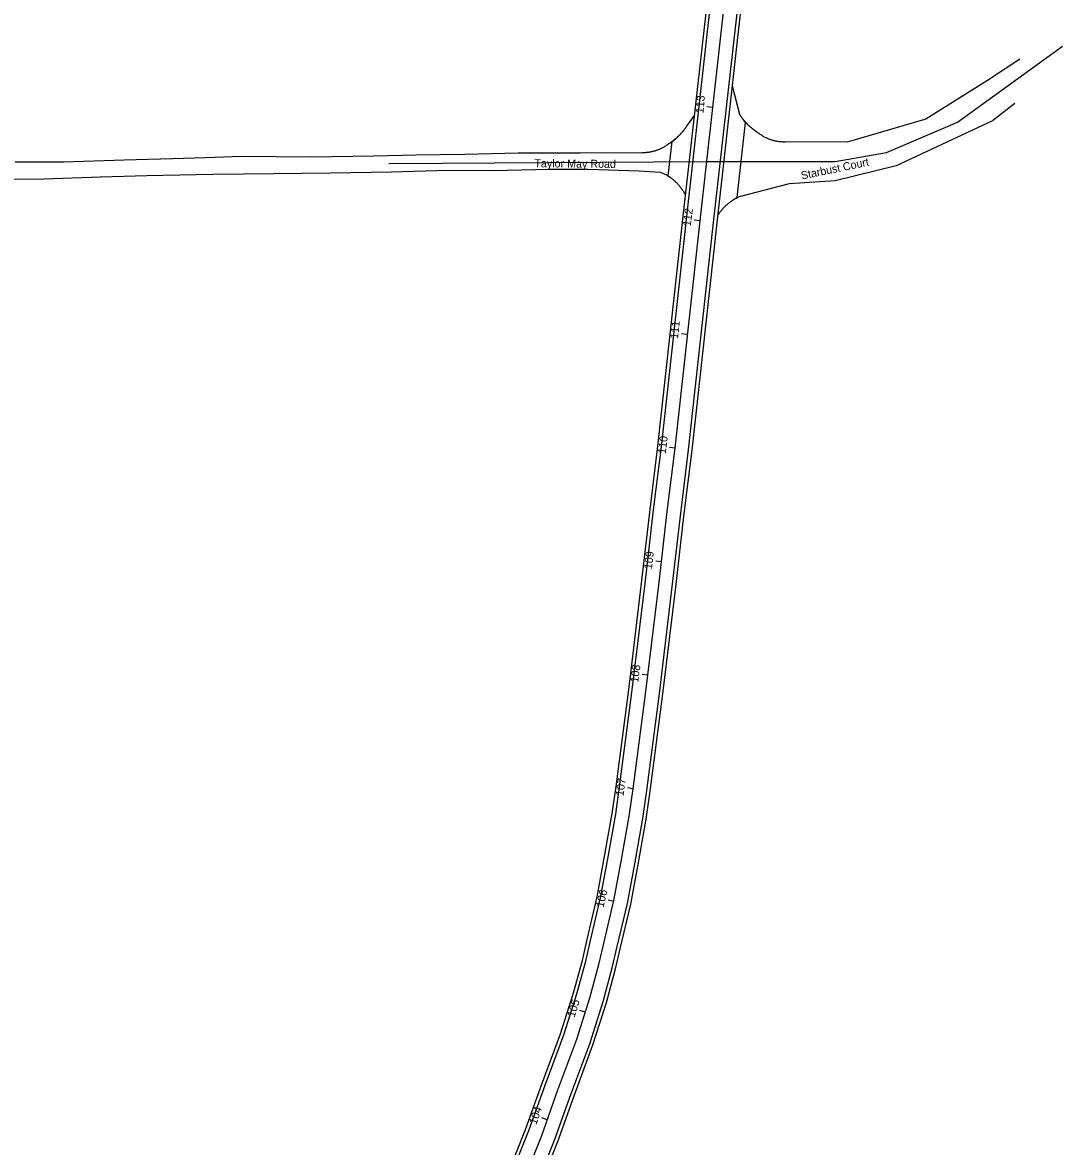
# Model space of a CAD drawing. Extents: x 2318076 to 2324211, y 613525 to 629939.
# Drawn here: x 2319710 to 2320620, y 624977 to 625960 of the extents above; entities that cross this region are included whole.
import ezdxf

# ---------------------------------------------------------------- set-up
doc = ezdxf.new("R2010")
doc.units = 0
for name, color, linetype in [('GE_P_CL_50', 7, 'Continuous'), ('GE_X_CL_50', 7, 'Continuous'), ('PV_P_EOP', 7, 'Continuous'), ('PV_P_Shoulder', 7, 'Continuous'), ('RS_Raster1', 7, 'Continuous')]:
    doc.layers.add(name, color=color, linetype=linetype)

msp = doc.modelspace()

# ---------------------------------------------------------------- linework, layer by layer
at = {"layer": 'GE_P_CL_50'}
for p, q in [((2320313.51, 625885.5), (2320308.52, 625885.92)), ((2320302.51, 625786.14), (2320297.55, 625786.8)), ((2320291.21, 625686.79), (2320286.24, 625687.31)), ((2320280.66, 625587.35), (2320275.69, 625587.96)), ((2320268.76, 625488.06), (2320263.79, 625488.64)), ((2320256.86, 625388.77), (2320251.9, 625389.39)), ((2320244.08, 625289.6), (2320239.13, 625290.3)), ((2320227.1, 625191.06), (2320222.24, 625192.22)), ((2320202.23, 625094.25), (2320197.46, 625095.76)), ((2320168.9, 624999.98), (2320164.19, 625001.66))]:
    msp.add_line(p, q, dxfattribs=at)
msp.add_lwpolyline([(2320140.16, 624926.58), (2320164.06, 624986.38), (2320178.23, 625026.18), (2320194.66, 625070.42), (2320206.22, 625106.83), (2320214.16, 625135.77), (2320218.35, 625154.25), (2320227.28, 625191.8), (2320233.59, 625226.06), (2320240.64, 625265.45), (2320244.08, 625289.6), (2320254.79, 625372.16), (2320256.86, 625388.77), (2320266.38, 625467.61), (2320273.88, 625532.13), (2320280.66, 625587.35), (2320302.51, 625786.14), (2320324.84, 625984.85)], dxfattribs=at)
at = {"layer": 'GE_X_CL_50'}
msp.add_line((2320030.25, 625836.28), (2320308.36, 625838.18), dxfattribs=at)
msp.add_lwpolyline([(2320308.36, 625838.18), (2320420.71, 625838.18), (2320465.73, 625845.99), (2320527.77, 625872.59), (2320619.58, 625938.92)], dxfattribs=at)
at = {"layer": 'PV_P_EOP'}
for p, q in [((2320337.34, 625879.18), (2320330.86, 625904.07)), ((2320291.58, 625870.03), (2320297.78, 625878.38))]:
    msp.add_line(p, q, dxfattribs=at)
for points in [[(2320129, 624931), (2320152.83, 624990.62), (2320166.95, 625030.28), (2320183.31, 625074.33), (2320194.71, 625110.23), (2320202.52, 625138.69), (2320206.66, 625156.96), (2320215.53, 625194.28), (2320221.78, 625228.2), (2320228.79, 625267.35), (2320232.19, 625291.22), (2320242.89, 625373.68), (2320244.95, 625390.24), (2320254.46, 625469.02), (2320261.96, 625533.55), (2320268.74, 625588.74), (2320290.58, 625787.47), (2320312.9, 625986.1)], [(2320151.32, 624922.16), (2320175.29, 624982.14), (2320189.51, 625022.08), (2320206.01, 625066.51), (2320217.73, 625103.43), (2320225.8, 625132.85), (2320230.04, 625151.54), (2320239.03, 625189.32), (2320245.4, 625223.92), (2320252.49, 625263.55), (2320255.97, 625287.98), (2320266.69, 625370.64), (2320268.77, 625387.31), (2320278.3, 625466.2), (2320285.8, 625530.71), (2320292.57, 625585.97), (2320314.44, 625784.81), (2320336.77, 625983.61)], [(2320342.39, 625872.41), (2320340.78, 625874.39), (2320340.66, 625874.53), (2320340.54, 625874.68), (2320340.43, 625874.82), (2320340.32, 625874.97), (2320340.2, 625875.11), (2320340.09, 625875.26), (2320339.98, 625875.4), (2320339.86, 625875.55), (2320339.75, 625875.7), (2320339.64, 625875.84), (2320339.53, 625875.99), (2320339.42, 625876.14), (2320339.31, 625876.29), (2320339.2, 625876.44), (2320339.1, 625876.59), (2320338.99, 625876.74), (2320338.88, 625876.89), (2320338.77, 625877.04), (2320338.67, 625877.19), (2320338.56, 625877.34), (2320338.46, 625877.49), (2320338.35, 625877.64), (2320338.25, 625877.79), (2320338.14, 625877.95), (2320338.04, 625878.1), (2320337.94, 625878.25), (2320337.84, 625878.41), (2320337.74, 625878.56), (2320337.63, 625878.71), (2320337.53, 625878.87), (2320337.43, 625879.02), (2320337.34, 625879.18)], [(2320278.11, 625855.59), (2320281.04, 625858.03), (2320281.18, 625858.15), (2320281.32, 625858.27), (2320281.46, 625858.39), (2320281.6, 625858.51), (2320281.74, 625858.63), (2320281.88, 625858.75), (2320282.02, 625858.87), (2320282.16, 625858.99), (2320282.3, 625859.11), (2320282.43, 625859.24), (2320282.57, 625859.36), (2320282.71, 625859.48), (2320282.84, 625859.61), (2320282.98, 625859.73), (2320283.11, 625859.86), (2320283.25, 625859.98), (2320283.38, 625860.11), (2320283.52, 625860.24), (2320283.65, 625860.36), (2320283.78, 625860.49), (2320283.92, 625860.62), (2320284.05, 625860.75), (2320284.18, 625860.88), (2320284.31, 625861.01), (2320284.44, 625861.14), (2320284.57, 625861.27), (2320284.7, 625861.4), (2320284.83, 625861.53), (2320284.96, 625861.66), (2320285.09, 625861.79), (2320285.22, 625861.92), (2320285.34, 625862.06), (2320285.47, 625862.19), (2320285.6, 625862.33), (2320285.72, 625862.46), (2320285.85, 625862.6), (2320285.97, 625862.73), (2320286.1, 625862.87), (2320286.22, 625863), (2320286.35, 625863.14), (2320286.47, 625863.28), (2320286.59, 625863.41), (2320286.71, 625863.55), (2320286.84, 625863.69), (2320286.96, 625863.83), (2320287.08, 625863.97), (2320287.2, 625864.11), (2320287.32, 625864.25), (2320287.44, 625864.39), (2320287.55, 625864.53), (2320287.67, 625864.67), (2320287.79, 625864.81), (2320287.91, 625864.96), (2320288.02, 625865.1), (2320288.14, 625865.24), (2320288.26, 625865.39), (2320288.37, 625865.53), (2320288.49, 625865.67), (2320288.6, 625865.82), (2320288.71, 625865.96), (2320288.83, 625866.11), (2320288.94, 625866.26), (2320289.05, 625866.4), (2320289.16, 625866.55), (2320289.27, 625866.7), (2320289.38, 625866.84), (2320289.49, 625866.99), (2320289.6, 625867.14), (2320289.71, 625867.29), (2320289.82, 625867.44), (2320289.93, 625867.59), (2320290.04, 625867.74), (2320290.14, 625867.89), (2320290.25, 625868.04), (2320290.35, 625868.19), (2320290.46, 625868.34), (2320290.56, 625868.49), (2320290.67, 625868.64), (2320290.77, 625868.8), (2320290.87, 625868.95), (2320290.98, 625869.1), (2320291.08, 625869.26), (2320291.18, 625869.41), (2320291.28, 625869.56), (2320291.38, 625869.72), (2320291.48, 625869.87), (2320291.58, 625870.03)], [(2320334.98, 625806.54), (2320342.39, 625872.41)], [(2320274.73, 625825.51), (2320278.11, 625855.59)], [(2320274.73, 625825.51), (2320276.76, 625824.08), (2320277.34, 625823.65), (2320277.92, 625823.21), (2320278.49, 625822.77), (2320279.05, 625822.31), (2320279.61, 625821.84), (2320280.15, 625821.37), (2320280.69, 625820.88), (2320281.22, 625820.39), (2320281.74, 625819.89), (2320282.25, 625819.37), (2320282.75, 625818.85), (2320283.24, 625818.32), (2320283.73, 625817.79), (2320284.2, 625817.24), (2320284.67, 625816.69), (2320285.12, 625816.12), (2320285.57, 625815.56), (2320286.01, 625814.98), (2320286.43, 625814.39), (2320286.85, 625813.8), (2320287.25, 625813.2), (2320287.65, 625812.6), (2320288.03, 625811.99), (2320289.96, 625808.8)], [(2320334.98, 625806.54), (2320331.51, 625804.43), (2320330.89, 625804.04), (2320330.29, 625803.64), (2320329.69, 625803.24), (2320329.1, 625802.82), (2320328.51, 625802.39), (2320327.94, 625801.95), (2320327.37, 625801.51), (2320326.81, 625801.05), (2320326.25, 625800.58), (2320325.71, 625800.11), (2320325.17, 625799.62), (2320324.64, 625799.13), (2320324.12, 625798.63), (2320323.61, 625798.11), (2320323.11, 625797.59), (2320322.62, 625797.06), (2320322.13, 625796.53), (2320321.66, 625795.98), (2320321.19, 625795.43), (2320320.74, 625794.86), (2320320.29, 625794.3), (2320319.85, 625793.72), (2320319.43, 625793.13), (2320319.01, 625792.54), (2320318.61, 625791.94), (2320318.21, 625791.34), (2320318.18, 625791.3)]]:
    msp.add_lwpolyline(points, dxfattribs=at)
at = {"layer": 'PV_P_Shoulder'}
for points in [[(2320126.21, 624932.11), (2320150.02, 624991.68), (2320164.13, 625031.31), (2320180.47, 625075.3), (2320191.83, 625111.09), (2320199.61, 625139.41), (2320203.74, 625157.64), (2320212.6, 625194.9), (2320218.83, 625228.74), (2320225.83, 625267.83), (2320229.21, 625291.62), (2320239.91, 625374.05), (2320241.97, 625390.6), (2320251.48, 625469.37), (2320258.99, 625533.91), (2320265.76, 625589.09), (2320287.6, 625787.8), (2320309.92, 625986.41)], [(2320154.11, 624921.05), (2320178.1, 624981.08), (2320192.33, 625021.05), (2320208.85, 625065.54), (2320220.61, 625102.57), (2320228.71, 625132.13), (2320232.96, 625150.86), (2320241.96, 625188.7), (2320248.35, 625223.38), (2320255.45, 625263.07), (2320258.94, 625287.58), (2320269.67, 625370.27), (2320271.75, 625386.95), (2320281.28, 625465.85), (2320288.77, 625530.35), (2320295.55, 625585.62), (2320317.42, 625784.48), (2320339.76, 625983.3)]]:
    msp.add_lwpolyline(points, dxfattribs=at)
at = {"layer": 'RS_Raster1'}
for p, q in [((2320337.34, 625879.18), (2320330.86, 625904.07)), ((2320291.58, 625870.03), (2320295.4, 625875.18))]:
    msp.add_line(p, q, dxfattribs=at)
for points in [[(2320582.17, 625927.61), (2320553.95, 625908.96), (2320499.97, 625875.32), (2320431.25, 625854.95), (2320377.43, 625855.23)], [(2320577.81, 625888.97), (2320558.36, 625873.67), (2320474.08, 625834.52), (2320420.65, 625821.28), (2320380.43, 625818.53), (2320337.96, 625807.69)], [(2320353.7, 625862.97), (2320353.54, 625863.07), (2320353.38, 625863.16), (2320353.23, 625863.26), (2320353.07, 625863.36), (2320352.92, 625863.46), (2320352.76, 625863.56), (2320352.61, 625863.66), (2320352.46, 625863.77), (2320352.3, 625863.87), (2320352.15, 625863.97), (2320352, 625864.07), (2320351.84, 625864.18), (2320351.69, 625864.28), (2320351.54, 625864.39), (2320351.39, 625864.49), (2320351.24, 625864.6), (2320351.09, 625864.7), (2320350.94, 625864.81), (2320350.79, 625864.92), (2320350.64, 625865.03), (2320350.49, 625865.14), (2320350.34, 625865.24), (2320350.19, 625865.35), (2320350.05, 625865.46), (2320349.9, 625865.57), (2320349.75, 625865.69), (2320349.6, 625865.8), (2320349.46, 625865.91), (2320349.31, 625866.02), (2320349.17, 625866.14), (2320349.02, 625866.25), (2320348.88, 625866.36), (2320348.73, 625866.48), (2320348.59, 625866.59), (2320348.45, 625866.71), (2320348.3, 625866.83), (2320348.16, 625866.94), (2320348.02, 625867.06), (2320347.88, 625867.18), (2320347.74, 625867.3), (2320347.59, 625867.42), (2320347.45, 625867.53), (2320347.31, 625867.65), (2320347.17, 625867.77), (2320347.04, 625867.9), (2320346.9, 625868.02), (2320346.76, 625868.14), (2320346.62, 625868.26), (2320346.48, 625868.38), (2320346.35, 625868.51), (2320346.21, 625868.63), (2320346.07, 625868.76), (2320345.94, 625868.88), (2320345.8, 625869.01), (2320345.67, 625869.13), (2320345.53, 625869.26), (2320345.4, 625869.38), (2320345.27, 625869.51), (2320345.13, 625869.64), (2320345, 625869.77), (2320344.87, 625869.9), (2320344.74, 625870.02), (2320344.61, 625870.15), (2320344.47, 625870.28), (2320344.34, 625870.41), (2320344.21, 625870.55), (2320344.09, 625870.68), (2320343.96, 625870.81), (2320343.83, 625870.94), (2320343.7, 625871.07), (2320343.57, 625871.21), (2320343.45, 625871.34), (2320343.32, 625871.47), (2320343.19, 625871.61), (2320343.07, 625871.74), (2320342.94, 625871.88), (2320342.82, 625872.02), (2320342.69, 625872.15), (2320342.57, 625872.29), (2320342.45, 625872.43), (2320342.32, 625872.56), (2320342.2, 625872.7), (2320342.08, 625872.84), (2320341.96, 625872.98), (2320341.84, 625873.12), (2320341.72, 625873.26), (2320341.6, 625873.4), (2320341.48, 625873.54), (2320341.36, 625873.68), (2320341.24, 625873.82), (2320341.13, 625873.96), (2320341.01, 625874.11), (2320340.89, 625874.25), (2320340.78, 625874.39), (2320340.66, 625874.53), (2320340.54, 625874.68), (2320340.43, 625874.82), (2320340.32, 625874.97), (2320340.2, 625875.11), (2320340.09, 625875.26), (2320339.98, 625875.4), (2320339.86, 625875.55), (2320339.75, 625875.7), (2320339.64, 625875.84), (2320339.53, 625875.99), (2320339.42, 625876.14), (2320339.31, 625876.29), (2320339.2, 625876.44), (2320339.1, 625876.59), (2320338.99, 625876.74), (2320338.88, 625876.89), (2320338.77, 625877.04), (2320338.67, 625877.19), (2320338.56, 625877.34), (2320338.46, 625877.49), (2320338.35, 625877.64), (2320338.25, 625877.79), (2320338.14, 625877.95), (2320338.04, 625878.1), (2320337.94, 625878.25), (2320337.84, 625878.41), (2320337.74, 625878.56), (2320337.63, 625878.71), (2320337.53, 625878.87), (2320337.43, 625879.02), (2320337.34, 625879.18)], [(2320275.22, 625853.82), (2320275.38, 625853.92), (2320275.53, 625854.02), (2320275.69, 625854.11), (2320275.84, 625854.21), (2320276, 625854.31), (2320276.15, 625854.41), (2320276.31, 625854.52), (2320276.46, 625854.62), (2320276.61, 625854.72), (2320276.77, 625854.82), (2320276.92, 625854.92), (2320277.07, 625855.03), (2320277.22, 625855.13), (2320277.38, 625855.24), (2320277.53, 625855.34), (2320277.68, 625855.45), (2320277.83, 625855.56), (2320277.98, 625855.66), (2320278.13, 625855.77), (2320278.28, 625855.88), (2320278.43, 625855.99), (2320278.57, 625856.1), (2320278.72, 625856.21), (2320278.87, 625856.32), (2320279.02, 625856.43), (2320279.16, 625856.54), (2320279.31, 625856.65), (2320279.46, 625856.76), (2320279.6, 625856.87), (2320279.75, 625856.99), (2320279.89, 625857.1), (2320280.04, 625857.22), (2320280.18, 625857.33), (2320280.33, 625857.45), (2320280.47, 625857.56), (2320280.61, 625857.68), (2320280.76, 625857.79), (2320280.9, 625857.91), (2320281.04, 625858.03), (2320281.18, 625858.15), (2320281.32, 625858.27), (2320281.46, 625858.39), (2320281.6, 625858.51), (2320281.74, 625858.63), (2320281.88, 625858.75), (2320282.02, 625858.87), (2320282.16, 625858.99), (2320282.3, 625859.11), (2320282.43, 625859.24), (2320282.57, 625859.36), (2320282.71, 625859.48), (2320282.84, 625859.61), (2320282.98, 625859.73), (2320283.11, 625859.86), (2320283.25, 625859.98), (2320283.38, 625860.11), (2320283.52, 625860.24), (2320283.65, 625860.36), (2320283.78, 625860.49), (2320283.92, 625860.62), (2320284.05, 625860.75), (2320284.18, 625860.88), (2320284.31, 625861.01), (2320284.44, 625861.14), (2320284.57, 625861.27), (2320284.7, 625861.4), (2320284.83, 625861.53), (2320284.96, 625861.66), (2320285.09, 625861.79), (2320285.22, 625861.92), (2320285.34, 625862.06), (2320285.47, 625862.19), (2320285.6, 625862.33), (2320285.72, 625862.46), (2320285.85, 625862.6), (2320285.97, 625862.73), (2320286.1, 625862.87), (2320286.22, 625863), (2320286.35, 625863.14), (2320286.47, 625863.28), (2320286.59, 625863.41), (2320286.71, 625863.55), (2320286.84, 625863.69), (2320286.96, 625863.83), (2320287.08, 625863.97), (2320287.2, 625864.11), (2320287.32, 625864.25), (2320287.44, 625864.39), (2320287.55, 625864.53), (2320287.67, 625864.67), (2320287.79, 625864.81), (2320287.91, 625864.96), (2320288.02, 625865.1), (2320288.14, 625865.24), (2320288.26, 625865.39), (2320288.37, 625865.53), (2320288.49, 625865.67), (2320288.6, 625865.82), (2320288.71, 625865.96), (2320288.83, 625866.11), (2320288.94, 625866.26), (2320289.05, 625866.4), (2320289.16, 625866.55), (2320289.27, 625866.7), (2320289.38, 625866.84), (2320289.49, 625866.99), (2320289.6, 625867.14), (2320289.71, 625867.29), (2320289.82, 625867.44), (2320289.93, 625867.59), (2320290.04, 625867.74), (2320290.14, 625867.89), (2320290.25, 625868.04), (2320290.35, 625868.19), (2320290.46, 625868.34), (2320290.56, 625868.49), (2320290.67, 625868.64), (2320290.77, 625868.8), (2320290.87, 625868.95), (2320290.98, 625869.1), (2320291.08, 625869.26), (2320291.18, 625869.41), (2320291.28, 625869.56), (2320291.38, 625869.72), (2320291.48, 625869.87), (2320291.58, 625870.03)], [(2320377.43, 625855.23), (2320376.81, 625855.21), (2320376.18, 625855.21), (2320375.56, 625855.21), (2320374.94, 625855.23), (2320374.32, 625855.25), (2320373.7, 625855.29), (2320373.08, 625855.33), (2320372.46, 625855.39), (2320371.85, 625855.46), (2320371.23, 625855.54), (2320370.61, 625855.63), (2320370, 625855.73), (2320369.39, 625855.84), (2320368.78, 625855.96), (2320368.17, 625856.09), (2320367.57, 625856.23), (2320366.97, 625856.38), (2320366.37, 625856.55), (2320365.77, 625856.72), (2320365.17, 625856.9), (2320364.58, 625857.09), (2320364, 625857.3), (2320363.41, 625857.51), (2320362.83, 625857.73), (2320362.26, 625857.96), (2320361.68, 625858.21), (2320361.11, 625858.46), (2320360.55, 625858.72), (2320359.99, 625858.99), (2320359.44, 625859.27), (2320358.89, 625859.56), (2320358.34, 625859.86), (2320357.8, 625860.17), (2320357.27, 625860.49), (2320356.74, 625860.82), (2320356.22, 625861.16), (2320355.7, 625861.5), (2320355.19, 625861.85), (2320354.69, 625862.22), (2320354.19, 625862.59), (2320353.7, 625862.97)], [(2320251.49, 625846.08), (2320252.11, 625846.06), (2320252.73, 625846.06), (2320253.35, 625846.06), (2320253.97, 625846.08), (2320254.59, 625846.1), (2320255.21, 625846.14), (2320255.83, 625846.19), (2320256.45, 625846.24), (2320257.07, 625846.31), (2320257.69, 625846.39), (2320258.3, 625846.48), (2320258.91, 625846.58), (2320259.53, 625846.69), (2320260.14, 625846.81), (2320260.74, 625846.94), (2320261.35, 625847.08), (2320261.95, 625847.23), (2320262.55, 625847.4), (2320263.15, 625847.57), (2320263.74, 625847.75), (2320264.33, 625847.94), (2320264.92, 625848.15), (2320265.5, 625848.36), (2320266.08, 625848.58), (2320266.66, 625848.82), (2320267.23, 625849.06), (2320267.8, 625849.31), (2320268.36, 625849.57), (2320268.92, 625849.84), (2320269.48, 625850.12), (2320270.03, 625850.42), (2320270.57, 625850.72), (2320271.11, 625851.02), (2320271.65, 625851.34), (2320272.17, 625851.67), (2320272.7, 625852.01), (2320273.21, 625852.35), (2320273.72, 625852.71), (2320274.23, 625853.07), (2320274.73, 625853.44), (2320275.22, 625853.82)], [(2319703.56, 625838), (2319746.02, 625837.73), (2319798.78, 625839.7), (2319841.09, 625840.88), (2319870.09, 625841.6), (2319901.38, 625842.83), (2319962.48, 625842.18), (2320016.95, 625843.25), (2320054.09, 625843.93), (2320096.8, 625844.68), (2320143.35, 625845.88), (2320197.67, 625845.8), (2320251.49, 625846.08)], [(2319679.43, 625822.59), (2319728.62, 625823.06), (2319778.28, 625824.85), (2319818.64, 625826.01), (2319876.41, 625827.15), (2319929.73, 625827.65), (2319979.45, 625828.3), (2320032.78, 625829.22), (2320082.32, 625830.71), (2320121.89, 625830.25), (2320170.8, 625831.35), (2320204.4, 625831.36), (2320249.29, 625829.95), (2320267.9, 625828.95)], [(2320267.9, 625828.95), (2320268.57, 625828.67), (2320269.23, 625828.39), (2320269.89, 625828.09), (2320270.55, 625827.78), (2320271.2, 625827.46), (2320271.84, 625827.12), (2320272.48, 625826.78), (2320273.11, 625826.43), (2320273.73, 625826.06), (2320274.35, 625825.69), (2320274.96, 625825.3), (2320275.57, 625824.9), (2320276.17, 625824.5), (2320276.76, 625824.08), (2320277.34, 625823.65), (2320277.92, 625823.21), (2320278.49, 625822.77), (2320279.05, 625822.31), (2320279.61, 625821.84), (2320280.15, 625821.37), (2320280.69, 625820.88), (2320281.22, 625820.39), (2320281.74, 625819.89), (2320282.25, 625819.37), (2320282.75, 625818.85), (2320283.24, 625818.32), (2320283.73, 625817.79), (2320284.2, 625817.24), (2320284.67, 625816.69), (2320285.12, 625816.12), (2320285.57, 625815.56), (2320286.01, 625814.98), (2320286.43, 625814.39), (2320286.85, 625813.8), (2320287.25, 625813.2), (2320287.65, 625812.6), (2320288.03, 625811.99), (2320288.26, 625811.61)], [(2320337.96, 625807.69), (2320337.29, 625807.41), (2320336.63, 625807.13), (2320335.97, 625806.83), (2320335.31, 625806.52), (2320334.66, 625806.2), (2320334.02, 625805.86), (2320333.38, 625805.52), (2320332.75, 625805.17), (2320332.13, 625804.8), (2320331.51, 625804.43), (2320330.89, 625804.04), (2320330.29, 625803.64), (2320329.69, 625803.24), (2320329.1, 625802.82), (2320328.51, 625802.39), (2320327.94, 625801.95), (2320327.37, 625801.51), (2320326.81, 625801.05), (2320326.25, 625800.58), (2320325.71, 625800.11), (2320325.17, 625799.62), (2320324.64, 625799.13), (2320324.12, 625798.63), (2320323.61, 625798.11), (2320323.11, 625797.59), (2320322.62, 625797.06), (2320322.13, 625796.53), (2320321.66, 625795.98), (2320321.19, 625795.43), (2320320.74, 625794.86), (2320320.29, 625794.3), (2320319.85, 625793.72), (2320319.43, 625793.13), (2320319.01, 625792.54), (2320318.61, 625791.94), (2320318.21, 625791.34), (2320318.18, 625791.3)]]:
    msp.add_lwpolyline(points, dxfattribs=at)

# ---------------------------------------------------------------- texts
at = {"layer": 'GE_P_CL_50'}
for s, rotation, p in [('113', 85.19309, (2320305.53, 625880.15)), ('Taylor May Road', 359.46155, (2320157.66, 625833.15)), ('Starbust Court', 11.78725, (2320391.59, 625822.3)), ('112', 82.43115, (2320294.3, 625781.26)), ('111', 84.05291, (2320283.26, 625682.84)), ('110', 83.00549, (2320272.47, 625582.22)), ('109', 83.36952, (2320260.42, 625481.32)), ('108', 82.88767, (2320248.49, 625382.21)), ('107', 81.90219, (2320235.54, 625282.88)), ('106', 76.62263, (2320218.02, 625185.29)), ('105', 72.38561, (2320192.75, 625089.19)), ('104', 70.40274, (2320159.29, 624995.34))]:
    msp.add_text(s, height=7, rotation=rotation, dxfattribs=at).set_placement(p)

doc.saveas('drawing.dxf')
